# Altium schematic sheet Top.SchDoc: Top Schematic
size A4; Date: Not used; ApprovedBy: Not used; CheckedBy: Not used; Author: Not used; CompanyName: STMicroelectronics; DrawnBy: Not used; Engineer: Not used; Organization: Not used; Address1: Not used; Address2: Not used; Address3: Not used; Address4: Not used; DocumentNumber: 2; Revision: Not used; SheetNumber: 2; SheetTotal: 4
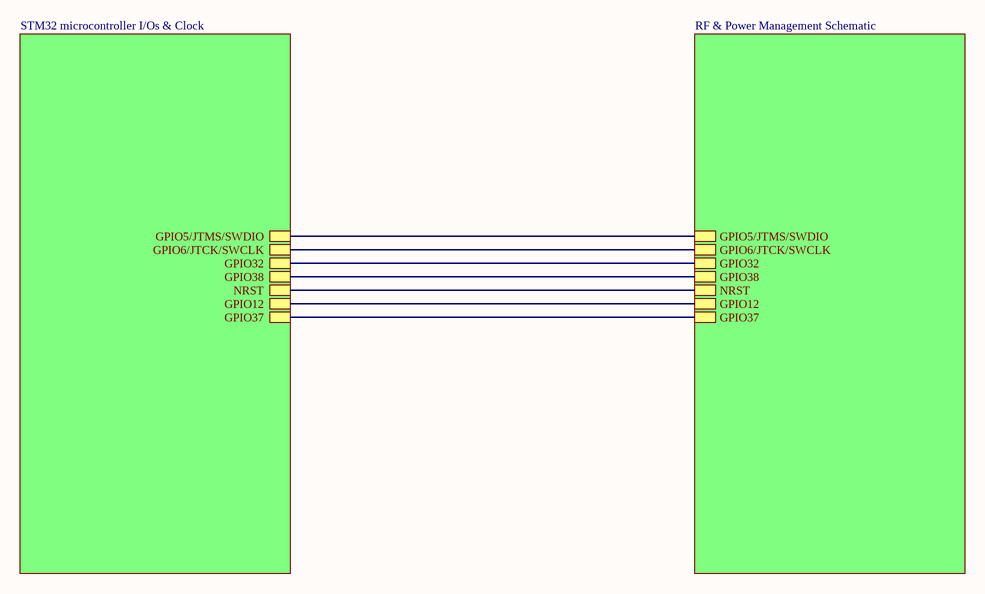
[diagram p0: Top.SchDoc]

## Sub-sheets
RF & Power Management Schematic = RF&Power_Management.SchDoc: GPIO5/JTMS/SWDIO, GPIO6/JTCK/SWCLK, GPIO32, GPIO38, NRST, GPIO12, GPIO37
STM32 microcontroller I/Os & Clock = MCU.SchDoc: GPIO37, GPIO5/JTMS/SWDIO, GPIO6/JTCK/SWCLK, GPIO32, GPIO38, NRST, GPIO12

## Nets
(unnamed): sheet STM32 microcontroller I/Os & Clock/GPIO37, sheet RF & Power Management Schematic/GPIO37
(unnamed): sheet STM32 microcontroller I/Os & Clock/GPIO5/JTMS/SWDIO, sheet RF & Power Management Schematic/GPIO5/JTMS/SWDIO  [a separate net that carries the same name]
(unnamed): sheet STM32 microcontroller I/Os & Clock/GPIO6/JTCK/SWCLK, sheet RF & Power Management Schematic/GPIO6/JTCK/SWCLK  [a separate net that carries the same name]
(unnamed): sheet STM32 microcontroller I/Os & Clock/GPIO32, sheet RF & Power Management Schematic/GPIO32  [a separate net that carries the same name]
(unnamed): sheet STM32 microcontroller I/Os & Clock/GPIO38, sheet RF & Power Management Schematic/GPIO38  [a separate net that carries the same name]
(unnamed): sheet STM32 microcontroller I/Os & Clock/NRST, sheet RF & Power Management Schematic/NRST  [a separate net that carries the same name]
(unnamed): sheet STM32 microcontroller I/Os & Clock/GPIO12, sheet RF & Power Management Schematic/GPIO12  [a separate net that carries the same name]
